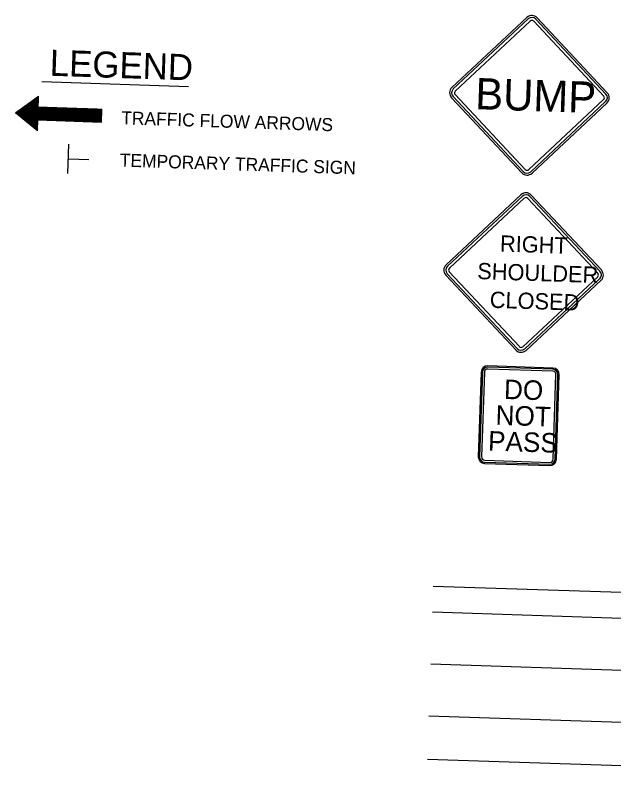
# Model space of a CAD drawing. Extents: x 977269 to 979191, y 1525946 to 1526973.
# Drawn here: x 977268.5 to 977544, y 1526615.5 to 1526972.6 of the extents above; entities that cross this region are included whole.
import ezdxf

# ---------------------------------------------------------------- set-up
doc = ezdxf.new("R2010")
doc.units = 0
for name, color, linetype in [('BDR_Plan Profile Grid 3', 7, 'Continuous'), ('R_Border', 7, 'Continuous'), ('R_Draft', 7, 'Continuous'), ('STAMP', 7, 'Continuous'), ('STAMP_PP', 7, 'Continuous')]:
    doc.layers.add(name, color=color, linetype=linetype)

msp = doc.modelspace()

# ---------------------------------------------------------------- linework, layer by layer
at = {"layer": 'BDR_Plan Profile Grid 3'}
for p, q in [((977469.57, 1526939.39), (977504.08, 1526971.67)), ((977470.19, 1526938.73), (977504.69, 1526971.01)), ((977508.19, 1526970.89), (977540.47, 1526936.39)), ((977508.85, 1526971.51), (977541.13, 1526937)), ((977505.62, 1526970.02), (977471.11, 1526937.74)), ((977539.48, 1526935.46), (977507.21, 1526969.97)), ((977502.35, 1526900.73), (977470.07, 1526935.23)), ((977471.06, 1526936.15), (977503.34, 1526901.65)), ((977501.69, 1526900.11), (977469.41, 1526934.62)), ((977504.93, 1526901.6), (977539.43, 1526933.87)), ((977540.35, 1526932.89), (977505.85, 1526900.61)), ((977540.97, 1526932.23), (977506.46, 1526899.95)), ((977516.07, 1526809.56), (977486.08, 1526810.56)), ((977516.09, 1526810.16), (977486.1, 1526811.16)), ((977483.01, 1526808.26), (977481.71, 1526769.28)), ((977483.61, 1526808.24), (977482.31, 1526769.26)), ((977484.51, 1526808.21), (977483.21, 1526769.23)), ((977516.04, 1526808.66), (977486.05, 1526809.66)), ((977516.19, 1526768.13), (977517.49, 1526807.11)), ((977517.09, 1526768.1), (977518.39, 1526807.08)), ((977517.69, 1526768.08), (977518.99, 1526807.06)), ((977484.66, 1526767.68), (977514.64, 1526766.68)), ((977484.61, 1526766.18), (977514.59, 1526765.18)), ((977484.63, 1526766.78), (977514.61, 1526765.78))]:
    msp.add_line(p, q, dxfattribs=at)
for centre, radius, start, end in [((977506.38, 1526969.2), 3.38, 43.0901, 133.0901), ((977506.38, 1526969.2), 2.48, 43.0901, 133.0901), ((977506.38, 1526969.2), 1.13, 43.0901, 133.0901), ((977471.88, 1526936.92), 3.38, 133.0901, 223.0901), ((977471.88, 1526936.92), 2.48, 133.0901, 223.0901), ((977471.88, 1526936.92), 1.13, 133.0901, 223.0901), ((977538.66, 1526934.7), 1.13, 313.0901, 43.0901), ((977538.66, 1526934.7), 2.48, 313.0901, 43.0901), ((977538.66, 1526934.7), 3.38, 313.0901, 43.0901), ((977504.16, 1526902.42), 3.38, 223.0901, 313.0901), ((977504.16, 1526902.42), 2.48, 223.0901, 313.0901), ((977504.16, 1526902.42), 1.13, 223.0901, 313.0901), ((977486, 1526808.16), 3, 88.0901, 178.0901), ((977486, 1526808.16), 2.4, 88.0901, 178.0901), ((977515.99, 1526807.16), 3, 358.0901, 88.0901), ((977486, 1526808.16), 1.5, 88.0901, 178.0901), ((977515.99, 1526807.16), 1.5, 358.0901, 88.0901), ((977515.99, 1526807.16), 2.4, 358.0901, 88.0901), ((977484.71, 1526769.18), 3, 178.0901, 268.0901), ((977484.71, 1526769.18), 2.4, 178.0901, 268.0901), ((977484.71, 1526769.18), 1.5, 178.0901, 268.0901), ((977514.69, 1526768.18), 3, 268.0901, 358.0901), ((977514.69, 1526768.18), 2.4, 268.0901, 358.0901), ((977514.69, 1526768.18), 1.5, 268.0901, 358.0901)]:
    msp.add_arc(centre, radius, start, end, dxfattribs=at)
at = {"layer": 'R_Border'}
for p, q in [((977278.95, 1526935.24), (977269.83, 1526926.71)), ((977279.16, 1526935.3), (977269.91, 1526926.64)), ((977279.16, 1526935.16), (977269.98, 1526926.58)), ((977279.15, 1526935.02), (977270.06, 1526926.51)), ((977273.9, 1526931.61), (977269.21, 1526927.22)), ((977274.53, 1526932.06), (977269.28, 1526927.16)), ((977275.16, 1526932.52), (977269.36, 1526927.09)), ((977275.79, 1526932.97), (977269.44, 1526927.03)), ((977276.42, 1526933.42), (977269.52, 1526926.96)), ((977277.06, 1526933.88), (977269.6, 1526926.9)), ((977277.69, 1526934.33), (977269.67, 1526926.84)), ((977278.32, 1526934.79), (977269.75, 1526926.77)), ((977279.15, 1526934.88), (977270.14, 1526926.45)), ((977279.14, 1526934.73), (977270.22, 1526926.39)), ((977279.14, 1526934.59), (977270.3, 1526926.32)), ((977279.13, 1526934.45), (977270.37, 1526926.26)), ((977279.13, 1526934.31), (977270.45, 1526926.19)), ((977279.12, 1526934.17), (977270.53, 1526926.13)), ((977279.12, 1526934.03), (977270.61, 1526926.07)), ((977279.11, 1526933.89), (977270.68, 1526926)), ((977279.11, 1526933.74), (977270.76, 1526925.94)), ((977279.1, 1526933.6), (977270.84, 1526925.87)), ((977279.1, 1526933.46), (977270.92, 1526925.81)), ((977279.1, 1526933.32), (977271, 1526925.74)), ((977279.09, 1526933.18), (977271.07, 1526925.68)), ((977279.09, 1526933.04), (977271.15, 1526925.62)), ((977279.08, 1526932.9), (977271.23, 1526925.55)), ((977279.08, 1526932.76), (977271.31, 1526925.49)), ((977279.07, 1526932.61), (977271.38, 1526925.42)), ((977279.07, 1526932.47), (977271.46, 1526925.36)), ((977279.06, 1526932.33), (977271.54, 1526925.29)), ((977279.06, 1526932.19), (977271.62, 1526925.23)), ((977279.05, 1526932.05), (977271.7, 1526925.17)), ((977279.05, 1526931.91), (977271.77, 1526925.1)), ((977279.04, 1526931.77), (977271.85, 1526925.04)), ((977279.04, 1526931.62), (977271.93, 1526924.97)), ((977279.03, 1526931.48), (977272.01, 1526924.91)), ((977268.84, 1526927.97), (977268.58, 1526927.73)), ((977269.47, 1526928.43), (977268.66, 1526927.67)), ((977270.11, 1526928.88), (977268.74, 1526927.61)), ((977270.74, 1526929.34), (977268.82, 1526927.54)), ((977271.37, 1526929.79), (977268.9, 1526927.48)), ((977272, 1526930.24), (977268.97, 1526927.41)), ((977272.63, 1526930.7), (977269.05, 1526927.35)), ((977273.26, 1526931.15), (977269.13, 1526927.28)), ((977279.03, 1526931.34), (977272.08, 1526924.85)), ((977279.02, 1526931.2), (977272.16, 1526924.78)), ((977279.02, 1526931.06), (977272.24, 1526924.72)), ((977279.01, 1526930.92), (977272.32, 1526924.65)), ((977279.01, 1526930.78), (977272.4, 1526924.59)), ((977279.01, 1526930.64), (977272.47, 1526924.52)), ((977279, 1526930.49), (977272.55, 1526924.46)), ((977279.05, 1526930.41), (977272.63, 1526924.4)), ((977279.2, 1526930.4), (977272.71, 1526924.33)), ((977279.34, 1526930.4), (977272.78, 1526924.27)), ((977279.48, 1526930.39), (977272.86, 1526924.2)), ((977279.62, 1526930.39), (977272.94, 1526924.14)), ((977279.76, 1526930.38), (977273.02, 1526924.08)), ((977279.9, 1526930.38), (977273.1, 1526924.01)), ((977280.04, 1526930.37), (977273.17, 1526923.95)), ((977280.19, 1526930.37), (977273.25, 1526923.88)), ((977280.33, 1526930.36), (977273.33, 1526923.82)), ((977280.47, 1526930.36), (977273.41, 1526923.75)), ((977280.61, 1526930.36), (977273.48, 1526923.69)), ((977280.75, 1526930.35), (977273.56, 1526923.63)), ((977280.89, 1526930.35), (977273.64, 1526923.56)), ((977281.03, 1526930.34), (977273.72, 1526923.5)), ((977281.17, 1526930.34), (977273.8, 1526923.43)), ((977281.32, 1526930.33), (977273.87, 1526923.37)), ((977281.46, 1526930.33), (977273.95, 1526923.31)), ((977281.6, 1526930.32), (977274.03, 1526923.24)), ((977281.74, 1526930.32), (977274.11, 1526923.18)), ((977281.88, 1526930.31), (977274.18, 1526923.11)), ((977282.02, 1526930.31), (977274.26, 1526923.05)), ((977282.16, 1526930.3), (977274.34, 1526922.98)), ((977282.31, 1526930.3), (977274.42, 1526922.92)), ((977282.45, 1526930.29), (977274.5, 1526922.86)), ((977282.59, 1526930.29), (977274.57, 1526922.79)), ((977282.73, 1526930.28), (977274.65, 1526922.73)), ((977282.87, 1526930.28), (977274.73, 1526922.66)), ((977283.01, 1526930.27), (977274.81, 1526922.6)), ((977283.15, 1526930.27), (977274.88, 1526922.54)), ((977283.29, 1526930.27), (977274.96, 1526922.47)), ((977283.44, 1526930.26), (977275.04, 1526922.41)), ((977283.58, 1526930.26), (977275.12, 1526922.34)), ((977283.72, 1526930.25), (977275.2, 1526922.28)), ((977283.86, 1526930.25), (977275.27, 1526922.21)), ((977284, 1526930.24), (977275.35, 1526922.15)), ((977284.14, 1526930.24), (977275.43, 1526922.09)), ((977284.28, 1526930.23), (977275.51, 1526922.02)), ((977284.43, 1526930.23), (977275.58, 1526921.96)), ((977284.57, 1526930.22), (977275.66, 1526921.89)), ((977284.71, 1526930.22), (977275.74, 1526921.83)), ((977284.85, 1526930.21), (977275.82, 1526921.77)), ((977284.99, 1526930.21), (977278.81, 1526924.43)), ((977285.13, 1526930.2), (977278.95, 1526924.42)), ((977285.27, 1526930.2), (977279.09, 1526924.42)), ((977285.41, 1526930.19), (977279.23, 1526924.41)), ((977285.56, 1526930.19), (977279.38, 1526924.41)), ((977285.7, 1526930.19), (977279.52, 1526924.4)), ((977285.84, 1526930.18), (977279.66, 1526924.4)), ((977285.98, 1526930.18), (977279.8, 1526924.39)), ((977286.12, 1526930.17), (977279.94, 1526924.39)), ((977286.26, 1526930.17), (977280.08, 1526924.38)), ((977286.4, 1526930.16), (977280.22, 1526924.38)), ((977286.55, 1526930.16), (977280.36, 1526924.38)), ((977286.69, 1526930.15), (977280.51, 1526924.37)), ((977286.83, 1526930.15), (977280.65, 1526924.37)), ((977286.97, 1526930.14), (977280.79, 1526924.36)), ((977287.11, 1526930.14), (977280.93, 1526924.36)), ((977287.25, 1526930.13), (977281.07, 1526924.35)), ((977287.39, 1526930.13), (977281.21, 1526924.35)), ((977287.54, 1526930.12), (977281.35, 1526924.34)), ((977287.68, 1526930.12), (977281.5, 1526924.34)), ((977287.82, 1526930.11), (977281.64, 1526924.33)), ((977287.96, 1526930.11), (977281.78, 1526924.33)), ((977288.1, 1526930.11), (977281.92, 1526924.32)), ((977288.24, 1526930.1), (977282.06, 1526924.32)), ((977288.38, 1526930.1), (977282.2, 1526924.31)), ((977288.52, 1526930.09), (977282.34, 1526924.31)), ((977288.67, 1526930.09), (977282.48, 1526924.3)), ((977288.81, 1526930.08), (977282.63, 1526924.3)), ((977288.95, 1526930.08), (977282.77, 1526924.3)), ((977289.09, 1526930.07), (977282.91, 1526924.29)), ((977289.23, 1526930.07), (977283.05, 1526924.29)), ((977289.37, 1526930.06), (977283.19, 1526924.28)), ((977289.51, 1526930.06), (977283.33, 1526924.28)), ((977289.66, 1526930.05), (977283.47, 1526924.27)), ((977289.8, 1526930.05), (977283.62, 1526924.27)), ((977289.94, 1526930.04), (977283.76, 1526924.26)), ((977290.08, 1526930.04), (977283.9, 1526924.26)), ((977290.22, 1526930.03), (977284.04, 1526924.25)), ((977290.36, 1526930.03), (977284.18, 1526924.25)), ((977290.5, 1526930.03), (977284.32, 1526924.24)), ((977290.64, 1526930.02), (977284.46, 1526924.24)), ((977290.79, 1526930.02), (977284.61, 1526924.23)), ((977290.93, 1526930.01), (977284.75, 1526924.23)), ((977291.07, 1526930.01), (977284.89, 1526924.22)), ((977291.21, 1526930), (977285.03, 1526924.22)), ((977291.35, 1526930), (977285.17, 1526924.22)), ((977291.49, 1526929.99), (977285.31, 1526924.21)), ((977291.63, 1526929.99), (977285.45, 1526924.21)), ((977291.78, 1526929.98), (977285.59, 1526924.2)), ((977291.92, 1526929.98), (977285.74, 1526924.2)), ((977292.06, 1526929.97), (977285.88, 1526924.19)), ((977292.2, 1526929.97), (977286.02, 1526924.19)), ((977292.34, 1526929.96), (977286.16, 1526924.18)), ((977292.48, 1526929.96), (977286.3, 1526924.18)), ((977292.62, 1526929.95), (977286.44, 1526924.17)), ((977292.76, 1526929.95), (977286.58, 1526924.17)), ((977292.91, 1526929.95), (977286.73, 1526924.16)), ((977293.05, 1526929.94), (977286.87, 1526924.16)), ((977293.19, 1526929.94), (977287.01, 1526924.15)), ((977293.33, 1526929.93), (977287.15, 1526924.15)), ((977293.47, 1526929.93), (977287.29, 1526924.14)), ((977293.61, 1526929.92), (977287.43, 1526924.14)), ((977293.75, 1526929.92), (977287.57, 1526924.13)), ((977293.9, 1526929.91), (977287.71, 1526924.13)), ((977294.04, 1526929.91), (977287.86, 1526924.13)), ((977294.18, 1526929.9), (977288, 1526924.12)), ((977294.32, 1526929.9), (977288.14, 1526924.12)), ((977294.46, 1526929.89), (977288.28, 1526924.11)), ((977294.6, 1526929.89), (977288.42, 1526924.11)), ((977294.74, 1526929.88), (977288.56, 1526924.1)), ((977294.88, 1526929.88), (977288.7, 1526924.1)), ((977295.03, 1526929.87), (977288.85, 1526924.09)), ((977295.17, 1526929.87), (977288.99, 1526924.09)), ((977295.31, 1526929.86), (977289.13, 1526924.08)), ((977295.45, 1526929.86), (977289.27, 1526924.08)), ((977295.59, 1526929.86), (977289.41, 1526924.07)), ((977295.73, 1526929.85), (977289.55, 1526924.07)), ((977295.87, 1526929.85), (977289.69, 1526924.06)), ((977296.02, 1526929.84), (977289.83, 1526924.06)), ((977296.16, 1526929.84), (977289.98, 1526924.05)), ((977296.3, 1526929.83), (977290.12, 1526924.05)), ((977296.44, 1526929.83), (977290.26, 1526924.05)), ((977296.58, 1526929.82), (977290.4, 1526924.04)), ((977296.72, 1526929.82), (977290.54, 1526924.04)), ((977296.86, 1526929.81), (977290.68, 1526924.03)), ((977297, 1526929.81), (977290.82, 1526924.03)), ((977297.15, 1526929.8), (977290.97, 1526924.02)), ((977297.29, 1526929.8), (977291.11, 1526924.02)), ((977297.43, 1526929.79), (977291.25, 1526924.01)), ((977297.57, 1526929.79), (977291.39, 1526924.01)), ((977297.71, 1526929.78), (977291.53, 1526924)), ((977297.85, 1526929.78), (977291.67, 1526924)), ((977297.99, 1526929.78), (977291.81, 1526923.99)), ((977298.14, 1526929.77), (977291.95, 1526923.99)), ((977298.28, 1526929.77), (977292.1, 1526923.98)), ((977298.42, 1526929.76), (977292.24, 1526923.98)), ((977298.56, 1526929.76), (977292.38, 1526923.97)), ((977298.7, 1526929.75), (977292.52, 1526923.97)), ((977298.84, 1526929.75), (977292.66, 1526923.97)), ((977298.98, 1526929.74), (977292.8, 1526923.96)), ((977299.13, 1526929.74), (977292.94, 1526923.96)), ((977299.27, 1526929.73), (977293.09, 1526923.95)), ((977299.41, 1526929.73), (977293.23, 1526923.95)), ((977299.55, 1526929.72), (977293.37, 1526923.94)), ((977299.69, 1526929.72), (977293.51, 1526923.94)), ((977299.83, 1526929.71), (977293.65, 1526923.93)), ((977299.97, 1526929.71), (977293.79, 1526923.93)), ((977300.11, 1526929.7), (977293.93, 1526923.92)), ((977300.26, 1526929.7), (977294.08, 1526923.92)), ((977300.4, 1526929.7), (977294.22, 1526923.91)), ((977300.54, 1526929.69), (977294.36, 1526923.91)), ((977300.68, 1526929.69), (977294.5, 1526923.9)), ((977300.82, 1526929.68), (977294.64, 1526923.9)), ((977300.96, 1526929.68), (977294.78, 1526923.89)), ((977301.1, 1526929.67), (977294.92, 1526923.89)), ((977301.25, 1526929.67), (977295.06, 1526923.89)), ((977301.39, 1526929.66), (977295.21, 1526923.88)), ((977301.53, 1526929.66), (977295.35, 1526923.88)), ((977301.67, 1526929.65), (977295.49, 1526923.87)), ((977301.81, 1526929.65), (977295.63, 1526923.87)), ((977301.95, 1526929.64), (977295.77, 1526923.86)), ((977302.09, 1526929.64), (977295.91, 1526923.86)), ((977302.23, 1526929.63), (977296.05, 1526923.85)), ((977302.38, 1526929.63), (977296.2, 1526923.85)), ((977302.52, 1526929.62), (977296.34, 1526923.84)), ((977302.66, 1526929.62), (977296.48, 1526923.84)), ((977302.8, 1526929.62), (977296.62, 1526923.83)), ((977302.94, 1526929.61), (977296.76, 1526923.83)), ((977303.08, 1526929.61), (977296.9, 1526923.82)), ((977303.22, 1526929.6), (977297.04, 1526923.82)), ((977303.37, 1526929.6), (977297.18, 1526923.81)), ((977303.51, 1526929.59), (977297.33, 1526923.81)), ((977303.65, 1526929.59), (977297.47, 1526923.8)), ((977303.79, 1526929.58), (977297.61, 1526923.8)), ((977303.93, 1526929.58), (977297.75, 1526923.8)), ((977304.07, 1526929.57), (977297.89, 1526923.79)), ((977304.21, 1526929.57), (977298.03, 1526923.79)), ((977304.35, 1526929.56), (977298.17, 1526923.78)), ((977304.5, 1526929.56), (977298.32, 1526923.78)), ((977304.64, 1526929.55), (977298.46, 1526923.77)), ((977304.78, 1526929.55), (977298.6, 1526923.77)), ((977304.92, 1526929.54), (977298.74, 1526923.76)), ((977305.06, 1526929.54), (977298.88, 1526923.76)), ((977305.2, 1526929.53), (977299.02, 1526923.75)), ((977305.34, 1526929.53), (977299.16, 1526923.75)), ((977305.49, 1526929.53), (977299.3, 1526923.74)), ((977305.63, 1526929.52), (977299.45, 1526923.74)), ((977305.77, 1526929.52), (977299.59, 1526923.73)), ((977305.91, 1526929.51), (977299.73, 1526923.73)), ((977306.05, 1526929.51), (977299.87, 1526923.72)), ((977306.19, 1526929.5), (977300.01, 1526923.72)), ((977306.33, 1526929.5), (977300.15, 1526923.72)), ((977306.47, 1526929.49), (977300.29, 1526923.71)), ((977306.62, 1526929.49), (977300.44, 1526923.71)), ((977306.76, 1526929.48), (977300.58, 1526923.7)), ((977306.9, 1526929.48), (977300.72, 1526923.7)), ((977307.04, 1526929.47), (977300.86, 1526923.69)), ((977307.18, 1526929.47), (977301, 1526923.69)), ((977307.32, 1526929.46), (977301.14, 1526923.68)), ((977307.46, 1526929.46), (977301.28, 1526923.68)), ((977307.61, 1526929.45), (977301.42, 1526923.67)), ((977307.75, 1526929.45), (977301.57, 1526923.67)), ((977307.89, 1526929.45), (977301.71, 1526923.66)), ((977308.03, 1526929.44), (977301.85, 1526923.66)), ((977308.17, 1526929.44), (977301.99, 1526923.65)), ((977308.31, 1526929.43), (977302.13, 1526923.65)), ((977308.32, 1526929.31), (977302.27, 1526923.64)), ((977308.32, 1526929.16), (977302.41, 1526923.64)), ((977308.32, 1526929.02), (977302.56, 1526923.64)), ((977308.31, 1526928.88), (977302.7, 1526923.63)), ((977308.31, 1526928.74), (977302.84, 1526923.63)), ((977308.3, 1526928.6), (977302.98, 1526923.62)), ((977308.3, 1526928.46), (977303.12, 1526923.62)), ((977308.29, 1526928.32), (977303.26, 1526923.61)), ((977308.29, 1526928.18), (977303.4, 1526923.61)), ((977308.28, 1526928.03), (977303.55, 1526923.6)), ((977308.28, 1526927.89), (977303.69, 1526923.6)), ((977278.8, 1526924.42), (977275.9, 1526921.7)), ((977278.79, 1526924.27), (977275.97, 1526921.64)), ((977308.27, 1526927.75), (977303.83, 1526923.59)), ((977308.27, 1526927.61), (977303.97, 1526923.59)), ((977308.26, 1526927.47), (977304.11, 1526923.58)), ((977308.26, 1526927.33), (977304.25, 1526923.58)), ((977308.25, 1526927.19), (977304.39, 1526923.57)), ((977308.25, 1526927.04), (977304.53, 1526923.57)), ((977308.24, 1526926.9), (977304.68, 1526923.56)), ((977308.24, 1526926.76), (977304.82, 1526923.56)), ((977308.24, 1526926.62), (977304.96, 1526923.56)), ((977308.23, 1526926.48), (977305.1, 1526923.55)), ((977308.23, 1526926.34), (977305.24, 1526923.55)), ((977308.22, 1526926.2), (977305.38, 1526923.54)), ((977308.22, 1526926.06), (977305.52, 1526923.54)), ((977308.21, 1526925.91), (977305.67, 1526923.53)), ((977308.21, 1526925.77), (977305.81, 1526923.53)), ((977308.2, 1526925.63), (977305.95, 1526923.52)), ((977308.2, 1526925.49), (977306.09, 1526923.52)), ((977308.19, 1526925.35), (977306.23, 1526923.51)), ((977308.19, 1526925.21), (977306.37, 1526923.51)), ((977308.18, 1526925.07), (977306.51, 1526923.5)), ((977308.18, 1526924.92), (977306.65, 1526923.5)), ((977308.17, 1526924.78), (977306.8, 1526923.49)), ((977308.17, 1526924.64), (977306.94, 1526923.49)), ((977308.16, 1526924.5), (977307.08, 1526923.48)), ((977308.16, 1526924.36), (977307.22, 1526923.48)), ((977308.16, 1526924.22), (977307.36, 1526923.48)), ((977278.79, 1526924.13), (977276.05, 1526921.57)), ((977278.78, 1526923.99), (977276.13, 1526921.51)), ((977278.78, 1526923.85), (977276.21, 1526921.44)), ((977278.77, 1526923.71), (977276.28, 1526921.38)), ((977278.77, 1526923.57), (977276.36, 1526921.32)), ((977278.77, 1526923.43), (977276.44, 1526921.25)), ((977278.76, 1526923.29), (977276.52, 1526921.19)), ((977278.76, 1526923.14), (977276.6, 1526921.12)), ((977278.75, 1526923), (977276.67, 1526921.06)), ((977278.75, 1526922.86), (977276.75, 1526921)), ((977278.74, 1526922.72), (977276.83, 1526920.93)), ((977278.74, 1526922.58), (977276.91, 1526920.87)), ((977278.73, 1526922.44), (977276.98, 1526920.8)), ((977278.73, 1526922.3), (977277.06, 1526920.74)), ((977278.72, 1526922.15), (977277.14, 1526920.67)), ((977278.72, 1526922.01), (977277.22, 1526920.61)), ((977278.71, 1526921.87), (977277.3, 1526920.55)), ((977278.71, 1526921.73), (977277.37, 1526920.48)), ((977278.7, 1526921.59), (977277.45, 1526920.42)), ((977278.7, 1526921.45), (977277.53, 1526920.35)), ((977278.69, 1526921.31), (977277.61, 1526920.29)), ((977278.69, 1526921.17), (977277.68, 1526920.22)), ((977278.69, 1526921.02), (977277.76, 1526920.16)), ((977278.68, 1526920.88), (977277.84, 1526920.1)), ((977278.68, 1526920.74), (977277.92, 1526920.03)), ((977308.15, 1526924.08), (977307.5, 1526923.47)), ((977308.15, 1526923.93), (977307.64, 1526923.47)), ((977308.14, 1526923.79), (977307.79, 1526923.46)), ((977308.14, 1526923.65), (977307.93, 1526923.46)), ((977308.13, 1526923.51), (977308.07, 1526923.45)), ((977278.67, 1526920.6), (977278, 1526919.97)), ((977278.67, 1526920.46), (977278.07, 1526919.9)), ((977278.66, 1526920.32), (977278.15, 1526919.84)), ((977278.66, 1526920.18), (977278.23, 1526919.78)), ((977278.65, 1526920.03), (977278.31, 1526919.71)), ((977278.65, 1526919.89), (977278.38, 1526919.65)), ((977278.64, 1526919.75), (977278.46, 1526919.58)), ((977278.64, 1526919.61), (977278.54, 1526919.52)), ((977278.63, 1526919.47), (977278.62, 1526919.45))]:
    msp.add_line(p, q, dxfattribs=at)
at = {"layer": 'R_Draft'}
msp.add_line((977280.73, 1526942.15), (977348.2, 1526939.9), dxfattribs=at)
at = {"layer": 'STAMP'}
for p, q in [((977268.55, 1526927.76), (977279.16, 1526935.39)), ((977279, 1526930.41), (977279.16, 1526935.39)), ((977279, 1526930.41), (977308.33, 1526929.43)), ((977308.13, 1526923.45), (977308.33, 1526929.43)), ((977278.63, 1526919.44), (977268.55, 1526927.76)), ((977278.63, 1526919.44), (977278.8, 1526924.43)), ((977278.8, 1526924.43), (977308.13, 1526923.45)), ((977292.72, 1526899.78), (977293.16, 1526913.24)), ((977293.13, 1526906.47), (977302.32, 1526906.16)), ((977460.97, 1526709.71), (977894.74, 1526695.24)), ((977460.57, 1526697.75), (977894.34, 1526683.28)), ((977459.77, 1526673.82), (977893.54, 1526659.36)), ((977458.97, 1526649.9), (977892.74, 1526635.43)), ((977458.31, 1526629.96), (977892.08, 1526615.49))]:
    msp.add_line(p, q, dxfattribs=at)
at = {"layer": 'STAMP_PP'}
for p, q in [((977466.85, 1526857.73), (977501.36, 1526890.01)), ((977467.49, 1526857.05), (977502, 1526889.33)), ((977505.44, 1526889.21), (977537.72, 1526854.71)), ((977506.13, 1526889.85), (977538.4, 1526855.35)), ((977468.39, 1526856.09), (977502.89, 1526888.37)), ((977504.48, 1526888.32), (977536.76, 1526853.81)), ((977498.97, 1526818.46), (977466.69, 1526852.96)), ((977499.65, 1526819.1), (977467.38, 1526853.61)), ((977500.61, 1526820), (977468.33, 1526854.5)), ((977536.71, 1526852.22), (977502.2, 1526819.94)), ((977537.6, 1526851.26), (977503.1, 1526818.98)), ((977538.25, 1526850.58), (977503.74, 1526818.3))]:
    msp.add_line(p, q, dxfattribs=at)
for centre, radius, start, end in [((977503.66, 1526887.55), 3.38, 43.0901, 133.0901), ((977503.66, 1526887.55), 2.44, 43.0901, 133.0901), ((977503.66, 1526887.55), 1.13, 43.0901, 133.0901), ((977469.16, 1526855.27), 3.38, 133.0901, 223.0901), ((977469.16, 1526855.27), 2.44, 133.0901, 223.0901), ((977469.16, 1526855.27), 1.12, 133.0901, 223.0901), ((977535.94, 1526853.04), 1.12, 313.0901, 43.0901), ((977535.94, 1526853.04), 2.44, 313.0901, 43.0901), ((977535.94, 1526853.04), 3.38, 313.0901, 43.0901), ((977501.43, 1526820.76), 3.38, 223.0901, 313.0901), ((977501.43, 1526820.76), 2.44, 223.0901, 313.0901), ((977501.43, 1526820.76), 1.13, 223.0901, 313.0901)]:
    msp.add_arc(centre, radius, start, end, dxfattribs=at)

# ---------------------------------------------------------------- texts
at = {"layer": 'BDR_Plan Profile Grid 3'}
for s, height, rotation, p in [('BUMP', 14.4, 358.0901, (977480.13, 1526929.44)), ('DO', 9, 358.0901, (977493.43, 1526795.91)), ('NOT', 9, 358.0497, (977489.55, 1526784.04)), ('PASS', 9, 358.0901, (977486.1, 1526772.14))]:
    msp.add_text(s, height=height, rotation=rotation, dxfattribs=at).set_placement(p)
at = {"layer": 'R_Draft'}
for s, height, p in [('LEGEND', 12, (977284.17, 1526944.84)), ('TRAFFIC FLOW ARROWS', 6, (977317.16, 1526922.49)), ('TEMPORARY TRAFFIC SIGN', 6, (977316.51, 1526903))]:
    msp.add_text(s, height=height, rotation=358.0901, dxfattribs=at).set_placement(p)
at = {"layer": 'STAMP_PP'}
for s, p in [('RIGHT', (977491.59, 1526863.83)), ('SHOULDER', (977481.14, 1526851.15)), ('CLOSED', (977486.89, 1526837.93))]:
    msp.add_text(s, height=7.5, rotation=358.0901, dxfattribs=at).set_placement(p)

doc.saveas('drawing.dxf')
